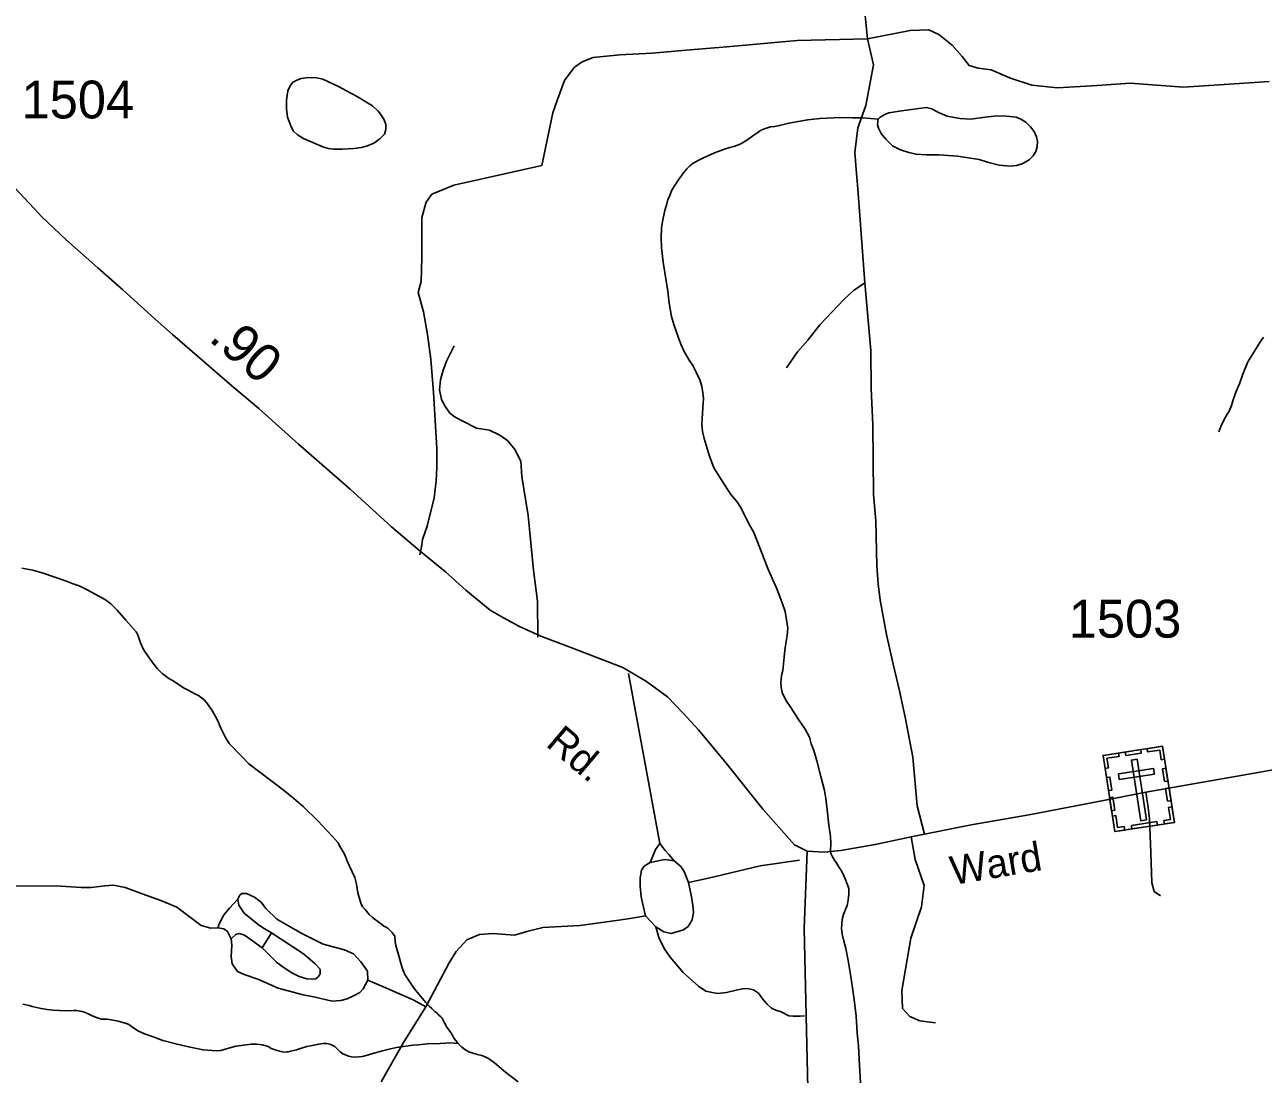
# Model space of a CAD drawing. Extents: x 2220236 to 2384410, y 720751 to 894131.
# Drawn here: x 2318475 to 2322567, y 871598 to 875066 of the extents above; entities that cross this region are included whole.
import ezdxf

# ---------------------------------------------------------------- set-up
doc = ezdxf.new("R2010")
doc.units = 0
doc.layers.add('Default', color=7, linetype='Continuous')

msp = doc.modelspace()

# ---------------------------------------------------------------- linework, layer by layer
at = {"layer": 'Default'}
for p, q in [((2320573, 872360.6), (2320470.2, 872923.1)), ((2320525.5, 872121.6), (2320560.5, 872085.2)), ((2319259.1, 872016.1), (2319290.7, 872065.3))]:
    msp.add_line(p, q, dxfattribs=at)
for points in [[(2321349.1, 876531.5), (2321291.2, 876528), (2321266.6, 876522.7), (2321240.2, 876513.9), (2321224.4, 876506.9), (2321206.9, 876492.8), (2321194.6, 876468.2), (2321191, 876452.4), (2321187.5, 876424.3), (2321187.5, 876382.1), (2321185.8, 876361), (2321194.6, 876285.4), (2321199.8, 876137.8), (2321210.4, 875926.9), (2321220.9, 875751.1), (2321233.2, 875603.5), (2321233.2, 875447), (2321242, 875294.1), (2321247.3, 875141.2), (2321259.8, 875019.9)], [(2319780.8, 873315), (2319786, 873341.4), (2319788.7, 873366), (2319804.5, 873409.9), (2319827.3, 873503.1), (2319834.3, 873559.3), (2319836.1, 873603.3), (2319836.1, 873666.5), (2319825.6, 873851.1), (2319816.8, 873961.8), (2319806.2, 874042.7), (2319792.2, 874118.3), (2319774.6, 874181.5), (2319785.2, 874218.4), (2319786.9, 874297.5), (2319786.9, 874429.4), (2319801, 874480.3), (2319820.3, 874506.7), (2319892.3, 874536.6), (2320183, 874601.6), (2320219.9, 874775.6), (2320235.7, 874819.6), (2320258.5, 874882.8), (2320290.2, 874925), (2320316.5, 874944.3), (2320353.4, 874958.4), (2320441.2, 874967.2), (2320548.4, 874972.5), (2320659.9, 874983), (2320795.2, 874993.6), (2321027, 875014.7), (2321259.8, 875019.9)], [(2321250.2, 874214), (2321228.1, 874524.3), (2321222.9, 874575.2), (2321217.6, 874643.8), (2321228.1, 874726.4), (2321254.5, 874800.2), (2321279.8, 874933.8), (2321259.8, 875019.9)], [(2321259.8, 875019.9), (2321400.3, 875048), (2321461.8, 875049.8), (2321495.1, 875034), (2321539, 874998.8), (2321572.4, 874961.9), (2321595.3, 874932), (2321625.1, 874923.3), (2321667.9, 874918), (2321732.3, 874889.9), (2321802.5, 874867), (2321886.8, 874858.2), (2322018.6, 874865.2), (2322127.5, 874874), (2322304, 874860), (2322437.5, 874868.8), (2322586.8, 874879.3)], [(2319344.3, 874847.8), (2319351.6, 874864.5), (2319359.7, 874875.6), (2319373.4, 874883.6), (2319387.8, 874889), (2319411.8, 874892.6), (2319438.7, 874891.1), (2319459.7, 874887.1), (2319511.7, 874862.8), (2319537.7, 874848.3), (2319571.4, 874830.9), (2319607.8, 874808.6), (2319623.8, 874798.6), (2319643.1, 874781.4), (2319654.1, 874767), (2319662.9, 874751.8), (2319668.5, 874736.4), (2319668.4, 874720), (2319663.8, 874705), (2319648.3, 874689.6), (2319627.9, 874674.9), (2319607.8, 874665.9), (2319587.8, 874660.9), (2319562.1, 874657.4), (2319523.6, 874655.1), (2319495, 874655.5), (2319477.5, 874657.2), (2319459.7, 874663), (2319395.7, 874690.8), (2319376.6, 874703), (2319361.6, 874716.4), (2319353.8, 874732.5), (2319343.6, 874760.9), (2319339.7, 874788.6), (2319340.3, 874817.4), (2319344.3, 874847.8)], [(2321294.3, 874754.7), (2321301.2, 874761.6), (2321316.4, 874769.6), (2321330.2, 874775), (2321372.3, 874782.5), (2321454.4, 874792.5), (2321472.3, 874789), (2321494.4, 874776.9), (2321522.3, 874764.8), (2321564.3, 874756.8), (2321600.4, 874755), (2321648.3, 874761), (2321688.4, 874765), (2321719.2, 874764.7), (2321750.4, 874761.2), (2321766.3, 874754.4), (2321782.5, 874744.3), (2321798.3, 874729.3), (2321810, 874713.4), (2321818.4, 874696.6), (2321821, 874681.9), (2321820.4, 874663), (2321815.8, 874648), (2321806.5, 874632.8), (2321793.8, 874620.1), (2321770.5, 874606.8), (2321751.9, 874601.2), (2321730.4, 874598.7), (2321694.4, 874602.8), (2321656.4, 874612.9), (2321628.3, 874620.7), (2321556.4, 874632.6), (2321496.4, 874636.5), (2321454.4, 874636.6), (2321420.3, 874638.4), (2321396.2, 874644.8), (2321368.3, 874652.7), (2321342.3, 874666.4), (2321320.2, 874688.5), (2321304.2, 874706.7), (2321296.3, 874724.4), (2321292.2, 874736.6), (2321294.3, 874754.7)], [(2321294.3, 874754.7), (2321244.3, 874758.4), (2321210.3, 874758.6), (2321176.2, 874760.4), (2321148.2, 874758.5), (2321102.3, 874756.6), (2321062.2, 874752.6), (2321030.3, 874747.1), (2321000.1, 874741), (2320969.2, 874733.1), (2320952.1, 874730.8), (2320938.8, 874728.7), (2320926.1, 874724.8), (2320916.1, 874721.2), (2320906.3, 874716.6), (2320890.7, 874706.1), (2320880.2, 874699.1), (2320864.1, 874687), (2320852.2, 874679.1), (2320838.3, 874672), (2320818.2, 874664.5), (2320804.1, 874660.8), (2320790.1, 874657), (2320754, 874643.1), (2320718.1, 874626.8), (2320704.1, 874620.4), (2320684, 874609), (2320672.1, 874600.3), (2320662.1, 874590.9), (2320651.1, 874577.2), (2320636.7, 874557), (2320628, 874544.3), (2320623.7, 874537.7), (2320614.1, 874522.5), (2320610.1, 874512.5), (2320610, 874510.7), (2320604, 874496.7), (2320600.1, 874489.1), (2320596, 874474.9), (2320590, 874452.5), (2320584, 874426.8), (2320579.3, 874396.4), (2320578, 874362.6), (2320578.8, 874329.8), (2320583.9, 874282.4), (2320593.9, 874220.6), (2320600.1, 874186.4), (2320603.9, 874146.3), (2320611.9, 874102.2), (2320620, 874076.4), (2320626, 874056.8), (2320636, 874028.6), (2320644, 874008.3), (2320653.9, 873986.7), (2320670, 873958.6), (2320682, 873940.3), (2320693.9, 873918.5), (2320706, 873892.8), (2320712, 873872.5), (2320715.9, 873850.6), (2320717.9, 873830.9), (2320715.9, 873800.4), (2320713.9, 873782.3), (2320712, 873746.2), (2320713.9, 873722.5), (2320719.9, 873698.9), (2320735.9, 873644.5), (2320751.9, 873602.6), (2320778, 873560.2), (2320807.9, 873514.6), (2320827.9, 873490.9), (2320840, 873472.3), (2320869.8, 873414.5), (2320883.9, 873388.1), (2320904, 873338.1), (2320930, 873270.1), (2320945.8, 873234.8), (2320957.9, 873208.1), (2320968, 873182.3), (2320977.9, 873156.5), (2320988, 873128.1), (2320992, 873100.4), (2320995.9, 873072.6), (2320993.9, 873047.9), (2320990, 873022.3), (2320985.9, 872999.9), (2320983.8, 872976.2), (2320979.8, 872932.5), (2320975.9, 872915.9), (2320973.8, 872904.4), (2320973.1, 872892.8), (2320973.7, 872876.4), (2320977.8, 872860.1), (2320989.9, 872834.4), (2321005.9, 872810.5), (2321031.9, 872770.5), (2321053.8, 872738.6)], [(2321060.5, 872335.9), (2321018.1, 872356.4), (2320915.3, 872473.3), (2320792, 872626.2), (2320701.4, 872736.7), (2320648.8, 872793.2), (2320598.7, 872845.9), (2320529.3, 872896), (2320450.9, 872942.2), (2320278.8, 873009), (2320180.5, 873046.3), (2320109.8, 873078.4), (2320057.2, 873106.7), (2320012.2, 873132.4), (2319932.5, 873197.9), (2319865.7, 873258.3), (2319780.9, 873326.4), (2319687.2, 873407.3), (2319550.3, 873531.9), (2319379.5, 873680.9), (2319248.4, 873797.9), (2319159.1, 873873.6), (2319028.1, 873986.7), (2318962.6, 874043.2), (2318906.1, 874093.3), (2318799.4, 874191), (2318716.6, 874262.9), (2318611.2, 874356.7), (2318531.7, 874431.7), (2318505.4, 874459.9), (2318441.6, 874528.9)], [(2320991.4, 873933.3), (2321028.7, 873985.9), (2321062.3, 874024.1), (2321101.9, 874074.5), (2321182.8, 874159.5), (2321212.5, 874187.7), (2321250.2, 874214)], [(2321447.7, 872392.2), (2321423.1, 872485.4), (2321409, 872646.3), (2321383.6, 872778.1), (2321364.8, 872865.8), (2321343.8, 872953.5), (2321322.7, 873051.3), (2321301.5, 873164.9), (2321294.9, 873218.8), (2321290.2, 873278.9), (2321286.7, 873426.8), (2321279.7, 873514.6), (2321277.3, 873744.5), (2321272, 873864.4), (2321270.6, 873990.4), (2321250.2, 874214)], [(2322420.1, 873721.8), (2322426.8, 873738.5), (2322438, 873762), (2322448.1, 873779.6), (2322454.1, 873789.6), (2322462.1, 873808.2), (2322466.1, 873823.8), (2322476.1, 873852.2), (2322488.2, 873879.7), (2322499.3, 873912.1), (2322516, 873952.3), (2322538.2, 873987.6), (2322556.2, 874016.3), (2322568.1, 874034)], [(2319894.1, 874005.8), (2319869.5, 873956.5), (2319857.2, 873924.9), (2319848.4, 873893.3), (2319844.9, 873859.9), (2319851.9, 873828.2), (2319862.4, 873807.1), (2319880, 873782.5), (2319897.6, 873770.2), (2319922.2, 873756.2), (2319967.8, 873733.3), (2320010, 873726.3), (2320045.1, 873710.5), (2320071.5, 873691.1), (2320094.3, 873663), (2320113.6, 873624.4), (2320117.1, 873573.4), (2320138.2, 873445.1), (2320155.8, 873264), (2320169, 873162.1), (2320170.7, 873042.6)], [(2318465.2, 873270.9), (2318501.2, 873264.2), (2318535.7, 873254), (2318609.2, 873228.4), (2318631.1, 873220.3), (2318655.2, 873212.1), (2318683.2, 873198.6), (2318741.4, 873166.4), (2318759.1, 873152.5), (2318780, 873131.9), (2318809.1, 873098.7), (2318843.3, 873060.7), (2318847.3, 873052.7), (2318852.5, 873037.3), (2318857.2, 873024.3), (2318865.1, 873006.6), (2318871.8, 872995.5), (2318883.5, 872977.7), (2318897.1, 872958.7), (2318913.2, 872937.9), (2318929.2, 872922.2), (2318951.3, 872905.9), (2318965.2, 872898.2), (2318983.3, 872886.8), (2319001.2, 872874.3), (2319017.2, 872866), (2319039.3, 872854.5), (2319049.2, 872850.1), (2319069.3, 872834.5), (2319079.2, 872822.5), (2319095.2, 872798.5), (2319105.3, 872780.1), (2319113.3, 872766.5), (2319123.3, 872742.3), (2319129.3, 872728.5), (2319138.8, 872709.3), (2319151.2, 872690.2), (2319191.3, 872649.8), (2319215.4, 872624.6), (2319329.3, 872538.2), (2319363.9, 872510), (2319394.6, 872482.7), (2319444.8, 872434.7), (2319473.3, 872403.9), (2319491.3, 872384), (2319509.3, 872364.3), (2319517.3, 872349.9), (2319527.4, 872333.9), (2319533.3, 872321.7), (2319539.3, 872306.3), (2319547.3, 872287.9), (2319565.3, 872248.4), (2319571.2, 872226.4), (2319575.4, 872198), (2319585.4, 872164), (2319591.3, 872151.8), (2319599.3, 872142.3), (2319613.3, 872126.5), (2319623.3, 872117.9), (2319629.3, 872112.4), (2319653.3, 872094.5), (2319661.3, 872088.3), (2319668.9, 872084.4), (2319675.3, 872079.8), (2319685.3, 872070.4), (2319689.4, 872066.4), (2319693.3, 872060), (2319697.3, 872054.5), (2319699.3, 872036.4), (2319701.4, 872024.3), (2319705.2, 872008), (2319710.8, 871989.3), (2319717.4, 871965.9), (2319723.4, 871946.3), (2319731.3, 871927.9), (2319741.4, 871911.1), (2319761.2, 871882.3), (2319799.3, 871836.2), (2319811.2, 871823.7), (2319819.8, 871815.8), (2319829.4, 871806.2), (2319837.4, 871800.2), (2319843.3, 871793.8), (2319849.3, 871788.2), (2319853.7, 871783.4), (2319863.4, 871765.8), (2319869.3, 871753.9), (2319881.4, 871737.9), (2319887.4, 871728.2), (2319893.3, 871716.2), (2319903.4, 871704.2), (2319906.9, 871700.4)], [(2321053.8, 872738.6), (2321067.9, 872712.2), (2321073.8, 872690.2), (2321081.9, 872668.3), (2321091.9, 872634.3), (2321105.8, 872582.3), (2321117.9, 872536.2), (2321121.8, 872509.9), (2321125.8, 872472.5), (2321131.8, 872421.9), (2321137.8, 872384.3), (2321137.9, 872362.1), (2321137.2, 872335.9), (2321138.5, 872327.7), (2321143.8, 872316.5), (2321150, 872306), (2321155.7, 872298), (2321165.8, 872282), (2321173.1, 872270.1), (2321181.3, 872254), (2321185.7, 872244.2), (2321193.8, 872224.1), (2321197.3, 872211.9), (2321197.8, 872203.7), (2321197.8, 872193.9), (2321195.8, 872174.2), (2321191.8, 872156), (2321185.8, 872141), (2321179.8, 872125.9), (2321175.8, 872110.2), (2321173.9, 872079.7), (2321175.8, 872061.7), (2321181.8, 872038.2), (2321187.8, 872013.8), (2321195.8, 871973.9), (2321203.7, 871928.2), (2321209.7, 871884.3), (2321215.7, 871845.9), (2321221.8, 871790.3), (2321225.7, 871733.9), (2321229.8, 871692.2), (2321233.6, 871627.5), (2321237.7, 871552.3)], [(2322768.6, 872634.8), (2322562.2, 872597.9), (2322179.3, 872531.1), (2322067.8, 872508.2), (2321799, 872457.3), (2321602.3, 872422.1), (2321447.7, 872392.2), (2321403.8, 872383.5), (2321285.2, 872357.1), (2321171.1, 872337.8), (2321117, 872332), (2321060.5, 872335.9)], [(2322227.6, 872188.4), (2322206.5, 872202.4), (2322199.5, 872230.5), (2322196, 872330.7), (2322191, 872442.6), (2322186.7, 872480.4), (2322179.3, 872531.1)], [(2320541, 872297.7), (2320550.3, 872319.6), (2320558.9, 872340.7), (2320573, 872360.6)], [(2320573, 872360.6), (2320590.9, 872338.3), (2320603.4, 872324.3), (2320620.6, 872304)], [(2321483.7, 871768.3), (2321432.8, 871775.3), (2321399.4, 871789.4), (2321374.8, 871815.7), (2321373.1, 871875.5), (2321402.9, 872047.7), (2321438.1, 872151.4), (2321446.8, 872221.7), (2321416.7, 872308.5), (2321403.8, 872383.5)], [(2321060.5, 872335.9), (2321050.2, 872080.2), (2321062.2, 871552.1), (2321052.8, 871389), (2321042.8, 871239.2), (2321010.3, 871121.5), (2320968.2, 871031.8), (2320943.6, 870984.4), (2320906.7, 870912.3), (2320849.6, 870792.8), (2320816.2, 870713.7), (2320782.9, 870627.6), (2320756.5, 870543.2), (2320739, 870436), (2320714.4, 870300.6), (2320647.6, 869833.1), (2320640.6, 869775.1), (2320639.7, 869694.3), (2320639.7, 869632.7), (2320648.5, 869420.1), (2320653.8, 869258.4)], [(2320525.5, 872121.6), (2320521.4, 872140.7), (2320511.3, 872185.2), (2320508.9, 872219.6), (2320508.2, 872247.7), (2320512.8, 872272.7), (2320521.1, 872285.5), (2320541, 872297.7)], [(2320541, 872297.7), (2320568.3, 872304), (2320590.1, 872307.9), (2320620.6, 872304)], [(2320620.6, 872304), (2320642.4, 872284.4), (2320653.7, 872268.2), (2320667.8, 872232.3)], [(2320667.8, 872232.3), (2320734.6, 872246.4), (2320904.9, 872286.8), (2321034.9, 872306.1)], [(2320560.5, 872085.2), (2320586.2, 872068.8), (2320611, 872063.9), (2320651, 872075.1), (2320666.7, 872086.4), (2320680.3, 872108.6), (2320684.2, 872132.6), (2320682.3, 872156.3), (2320678.4, 872184.4), (2320667.8, 872232.3)], [(2318443, 872219.6), (2318578.2, 872221.3), (2318660.8, 872216), (2318694.1, 872216), (2318739.8, 872221.3), (2318767.9, 872223.1), (2318806.6, 872216), (2318862.8, 872194.9), (2318924.2, 872172.1), (2318976.9, 872151), (2319022.6, 872115.9), (2319057.7, 872089.5), (2319089.4, 872080.7), (2319113.9, 872082.5)], [(2319608.6, 871908.9), (2319606.9, 871938.8), (2319585.8, 871970.4), (2319561.2, 871996.8), (2319531.3, 872009.1), (2319461.1, 872028.4), (2319390.8, 872063.6), (2319308.3, 872111), (2319271.4, 872146.2), (2319255.6, 872167.3), (2319234.5, 872183.1), (2319208.1, 872196.1), (2319192.3, 872195.4), (2319185.7, 872189.9), (2319178.7, 872177.5)], [(2319178.7, 872177.5), (2319151.6, 872146.8), (2319134.2, 872126.5), (2319124.1, 872109.1), (2319114.6, 872090.2), (2319113.9, 872082.5)], [(2319178.7, 872177.5), (2319182.8, 872156.9), (2319199.4, 872130.4), (2319245.8, 872093.1), (2319261, 872083), (2319290.7, 872065.3)], [(2319800.1, 871821), (2319877.4, 871966.9), (2319900.2, 872003.8), (2319935.3, 872042.5), (2319977.5, 872060), (2320021.4, 872063.6), (2320093.4, 872058.3), (2320133.8, 872070.6), (2320186.5, 872082.9), (2320309.5, 872089.9), (2320437.7, 872107.5), (2320481.6, 872114.5), (2320525.5, 872121.6)], [(2319113.9, 872082.5), (2319132.6, 872079.4), (2319144.9, 872070.6), (2319157.2, 872046)], [(2319290.7, 872065.3), (2319396.1, 871996.8), (2319434.7, 871963.4), (2319450.5, 871945.8), (2319450.5, 871930), (2319445.3, 871921.2), (2319436.5, 871914.2), (2319424.2, 871912.4), (2319406.6, 871914.2), (2319382, 871921.2), (2319357.4, 871933.5), (2319329.3, 871952.8), (2319306.5, 871968.6), (2319283.7, 871991.5), (2319259.1, 872016.1)], [(2320560.5, 872085.2), (2320570, 872050.7), (2320587.6, 872014.3), (2320607.5, 871985.1), (2320650.8, 871934.7), (2320701.2, 871889), (2320725.8, 871872.6), (2320741, 871870.2), (2320764.4, 871865.5), (2320793.7, 871869), (2320825.3, 871876.1), (2320846.4, 871880.8), (2320862.8, 871881.9), (2320882.7, 871877.3), (2320899.1, 871866.7), (2320913.1, 871848), (2320928.4, 871830.4), (2320942.4, 871816.3), (2320956.5, 871810.5), (2320974, 871804.6), (2320999.8, 871791.7), (2321013.9, 871790.5), (2321037.3, 871790.5), (2321051.3, 871791.7)], [(2319259.1, 872016.1), (2319215.2, 872047.7), (2319201.1, 872058.3), (2319183.5, 872063.6), (2319171.9, 872060.5), (2319157.2, 872046)], [(2319157.2, 872046), (2319159, 872024.9), (2319157.2, 871988), (2319160.7, 871963.4), (2319178.4, 871937.9), (2319199.4, 871928.2), (2319245, 871912.4), (2319311.8, 871882.5), (2319394.4, 871860.3), (2319434.7, 871852.6), (2319490.9, 871840.3), (2319519, 871842.1), (2319540.1, 871847.4), (2319561.2, 871857.9), (2319582.3, 871868.5), (2319592.8, 871880.8), (2319608.6, 871908.9)], [(2319608.6, 871908.9), (2319670.2, 871882.8), (2319757.9, 871843.9), (2319800.1, 871821)], [(2319906.9, 871700.4), (2319883.3, 871701.8), (2319847.3, 871700.3), (2319806.2, 871698.6), (2319775.3, 871695.8), (2319757.3, 871694.2), (2319726.1, 871690.6), (2319703.6, 871687), (2319683.2, 871682.2), (2319656.9, 871675.3), (2319625.4, 871666.6), (2319603.3, 871659.9), (2319591.2, 871657), (2319579.2, 871655.7), (2319569, 871655.3), (2319555.2, 871656.3), (2319544.5, 871658.5), (2319535.1, 871662.1), (2319525.8, 871665.9), (2319517.1, 871672), (2319507.1, 871682.4), (2319499.2, 871690.3), (2319485.9, 871697.1), (2319473.2, 871699.8), (2319461.2, 871700.1), (2319445.4, 871697.9), (2319431, 871694.9), (2319407.2, 871689.7), (2319393.1, 871685.9), (2319372.8, 871679.3), (2319363.1, 871676.5), (2319353.2, 871674.3), (2319345, 871672.3), (2319341.1, 871672.2), (2319332.1, 871671.8), (2319321.2, 871673.9), (2319305.2, 871678.1), (2319289.1, 871684), (2319279.1, 871690.2), (2319261, 871696.1), (2319241.2, 871697.7), (2319223.2, 871697.7), (2319198.9, 871694.3), (2319172.8, 871690.7), (2319145.1, 871683.9), (2319123, 871676.4), (2319107, 871675.8), (2319063.9, 871679), (2319021.1, 871687.8), (2318978.5, 871697.5), (2318930.9, 871710.4), (2318902.1, 871720.6), (2318871, 871731.7), (2318849, 871742.2), (2318831.1, 871753.9), (2318818.9, 871762.4), (2318811, 871766.3), (2318799, 871769.8), (2318783.1, 871773.3), (2318760.9, 871778), (2318747, 871780.1), (2318733, 871780.3), (2318729, 871780.1), (2318715, 871784.3), (2318705, 871788.1), (2318693, 871794.2), (2318685, 871797.9), (2318674.8, 871802.5), (2318664.9, 871806.1), (2318657.4, 871807.4), (2318648.4, 871808.8), (2318635, 871809.1), (2318617, 871808.3), (2318589.5, 871809.6), (2318568.9, 871810.4), (2318549, 871812.1), (2318528.9, 871815.3), (2318499, 871822.3), (2318489, 871826.1), (2318468.8, 871830.1)], [(2319652.5, 871573.2), (2319726.3, 871703.2), (2319800.1, 871821)], [(2319906.9, 871700.4), (2319911.3, 871695.6), (2319919.3, 871687.7), (2319929.4, 871679.9), (2319942.1, 871672.2), (2319955.3, 871667.9), (2319971.3, 871663.6), (2319985.4, 871660.2), (2319995.8, 871656.4), (2320007.2, 871650.3), (2320027.4, 871636.3), (2320063.3, 871605.7), (2320105.4, 871573.9)]]:
    msp.add_lwpolyline(points, dxfattribs=at)
for points in [[(2322037.8, 872651.9), (2322234.6, 872682.2), (2322273.4, 872430.6), (2322076.6, 872400.3)], [(2322241.3, 872639.4), (2322230, 872637.7), (2322225.1, 872669.5), (2322185.1, 872663.3), (2322183.4, 872674.3), (2322234.7, 872682.2)], [(2322044.4, 872609.1), (2322055.6, 872610.8), (2322050.7, 872642.6), (2322090.8, 872648.8), (2322089.1, 872659.8), (2322037.8, 872651.9)], [(2322111, 872663.2), (2322162.2, 872671.1), (2322164, 872659.8), (2322112.8, 872651.9)], [(2322150, 872639.6), (2322131.6, 872636.7), (2322162.4, 872436.3), (2322180.9, 872439.1)], [(2322088.5, 872590.9), (2322091.4, 872572.4), (2322207.7, 872590.3), (2322204.9, 872608.8)], [(2322241.1, 872565.4), (2322234.5, 872608.2), (2322245.8, 872610), (2322252.4, 872567.2)], [(2322055.7, 872535.8), (2322049.1, 872578.6), (2322060.3, 872580.4), (2322066.9, 872537.5)], [(2322065.9, 872469.4), (2322059.3, 872512.2), (2322070.6, 872513.9), (2322077.2, 872471.1)], [(2322251.1, 872500.3), (2322244.5, 872543.1), (2322255.8, 872544.8), (2322262.4, 872502)], [(2322240.6, 872425.5), (2322238.9, 872436.9), (2322260.6, 872440.2), (2322254.4, 872480.2), (2322265.4, 872481.9), (2322273.4, 872430.6)], [(2322109.3, 872405.3), (2322107.5, 872416.7), (2322085.8, 872413.3), (2322079.6, 872453.3), (2322068.6, 872451.6), (2322076.5, 872400.3)], [(2322131.6, 872420.3), (2322215.5, 872433.3), (2322217.2, 872422), (2322133.4, 872409.1)]]:
    msp.add_lwpolyline(points, close=True, dxfattribs=at)

# ---------------------------------------------------------------- texts
for s, p in [('1504', (2318464.4, 874756.9)), ('1503', (2321924.5, 873041.2))]:
    msp.add_text(s, height=125, dxfattribs=at).set_placement(p)
for s, height, rotation, p in [('.90', 125, 319.2142, (2319079.4, 874025)), ('Rd.', 95, 319.7056, (2320193.1, 872685.6)), ('Ward', 95, 9.5356, (2321541.5, 872223.4))]:
    msp.add_text(s, height=height, rotation=rotation, dxfattribs=at).set_placement(p)

doc.saveas('drawing.dxf')
